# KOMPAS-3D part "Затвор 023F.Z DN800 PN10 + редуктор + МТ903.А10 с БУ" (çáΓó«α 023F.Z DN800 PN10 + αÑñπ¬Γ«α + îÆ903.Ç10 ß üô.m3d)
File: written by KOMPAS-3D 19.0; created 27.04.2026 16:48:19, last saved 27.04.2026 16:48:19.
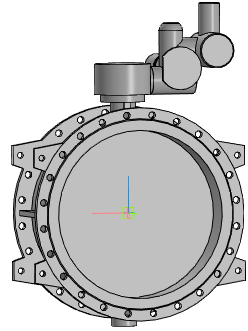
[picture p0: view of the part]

Document properties: Полное имя файла: ..\..\Затвор 023F.Z DN400-DN1600 + редуктор + МТ903\Затвор 023F.Z DN800 PN10 + редуктор + МТ903.А10 с БУ.a3d

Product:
- Part/product: Затвор 023F.Z DN800 PN10 + редуктор + МТ903.А10 с БУ
    Масса: 873.87

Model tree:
1. Операция без истории:1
